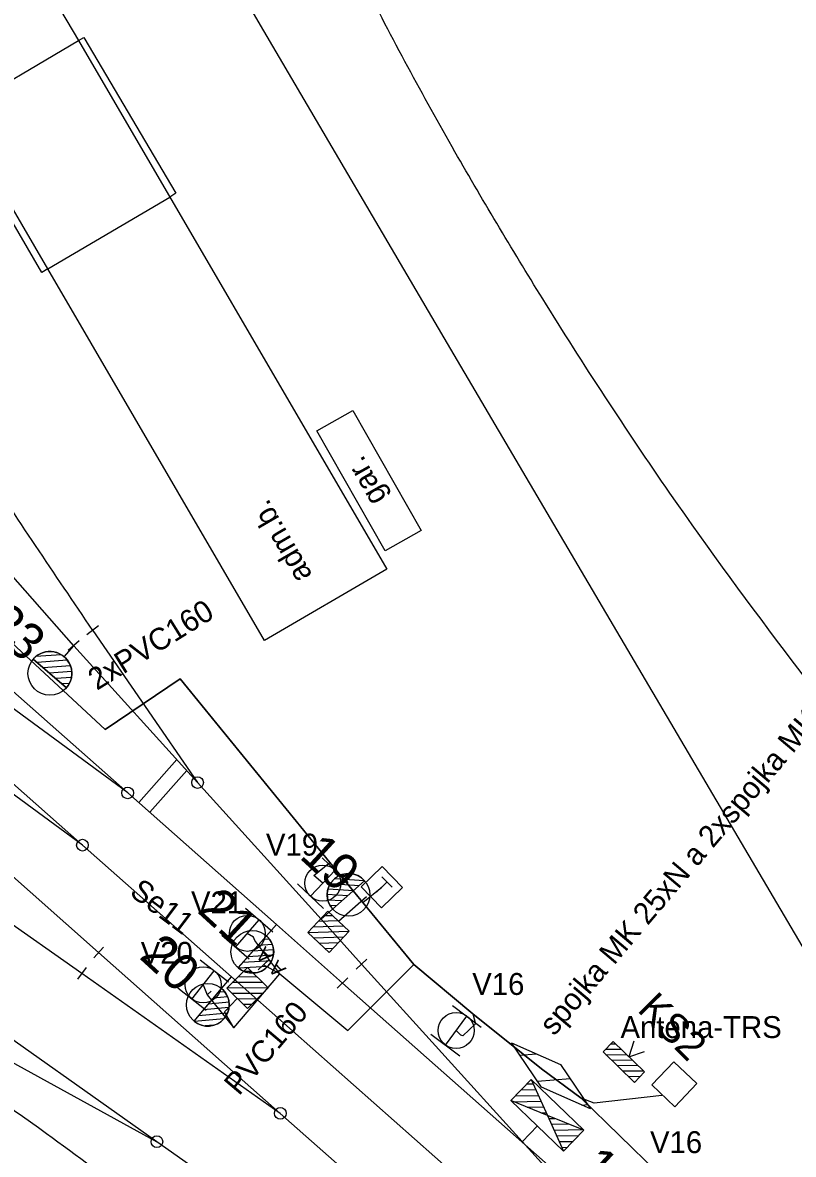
# Model space of a CAD drawing. Extents: x -496570 to -495506, y -1089156 to -1088046.
# Drawn here: x -495999 to -495946.2, y -1088619.5 to -1088542 of the extents above; entities that cross this region are included whole.
import ezdxf

# ---------------------------------------------------------------- set-up
doc = ezdxf.new("R2010")
doc.units = 0
for name, color, linetype in [('11', 7, 'Continuous'), ('14', 7, 'Continuous'), ('15', 7, 'Continuous'), ('20', 7, 'Continuous'), ('27', 7, 'Continuous'), ('39', 7, 'Continuous'), ('54', 7, 'Continuous'), ('PŘÍSTUPOVÉ_CESTY', 7, 'Continuous'), ('PŮVODNÍ_NÁVRH', 7, 'Continuous'), ('SEE', 7, 'Continuous')]:
    doc.layers.add(name, color=color, linetype=linetype)

msp = doc.modelspace()

# ---------------------------------------------------------------- linework, layer by layer
at = {"layer": '11'}
for points in [[(-495991.022, -1088595.386), (-495988.427, -1088592.439)], [(-495990.272, -1088596.046), (-495987.752, -1088593.184)]]:
    msp.add_lwpolyline(points, dxfattribs=at)
at = {"layer": '14'}
for p, q in [((-495993.785, -1088605.649), (-496022.225, -1088580.492)), ((-495994.931, -1088607.083), (-496005.328, -1088599.803)), ((-495978.542, -1088603.36), (-495975.783, -1088606.452)), ((-495981.593, -1088603.731), (-495977.082, -1088607.738))]:
    msp.add_line(p, q, dxfattribs=at)
for points in [[(-495941.228, -1088612.636), (-495960.706, -1088579.532), (-495969.885, -1088563.939), (-495982.474, -1088542.537), (-495998.352, -1088515.291)], [(-495984.692, -1088607.313), (-495963.796, -1088625.807), (-495948.204, -1088639.594)]]:
    msp.add_lwpolyline(points, dxfattribs=at)
for points in [[(-495937.589, -1088596.936), (-495954.664, -1088574.181), (-495963.373, -1088560.878), (-495969.575, -1088550.475), (-495975.882, -1088538.692), (-495984.212, -1088520.604)], [(-495994.179, -1088583.585), (-496001.925, -1088571.928), (-496007.411, -1088562.975), (-496027.558, -1088528.593)], [(-495939.964, -1088690.857), (-495942.044, -1088686.532), (-495949.093, -1088672.316), (-495953.81, -1088663.645), (-495962.754, -1088650.285), (-495972.743, -1088638.936), (-495985.077, -1088627.584), (-495997.355, -1088618.062), (-496006.199, -1088611.844)]]:
    msp.add_spline(points, degree=3, dxfattribs=at)
at = {"layer": '15'}
for p, q in [((-495978.475, -1088599.157), (-495976.688, -1088600.854)), ((-495979.278, -1088601.792), (-495977.582, -1088600.006)), ((-495980.172, -1088600.944), (-495978.385, -1088602.641)), ((-495983.721, -1088602.605), (-495981.862, -1088604.222)), ((-495984.409, -1088605.272), (-495982.791, -1088603.414)), ((-495978.732, -1088603.512), (-495977.405, -1088603.468)), ((-495978.37, -1088603.125), (-495977.791, -1088603.106)), ((-495979.457, -1088604.286), (-495976.63, -1088604.193)), ((-495979.095, -1088603.9), (-495977.017, -1088603.831)), ((-495985.338, -1088604.464), (-495983.479, -1088606.081)), ((-495979.07, -1088604.649), (-495976.992, -1088604.58)), ((-495978.682, -1088605.012), (-495977.355, -1088604.968)), ((-495978.296, -1088605.374), (-495977.717, -1088605.355)), ((-495986.833, -1088606.141), (-495984.896, -1088607.664)), ((-495987.387, -1088608.84), (-495985.865, -1088606.902)), ((-495982.926, -1088607.326), (-495984.254, -1088607.332)), ((-495983.303, -1088606.953), (-495983.881, -1088606.956)), ((-495988.356, -1088608.078), (-495986.419, -1088609.601)), ((-495982.172, -1088608.072), (-495985.001, -1088608.086)), ((-495982.549, -1088607.699), (-495984.628, -1088607.71)), ((-495982.545, -1088608.449), (-495984.624, -1088608.459)), ((-495982.919, -1088608.826), (-495984.247, -1088608.833)), ((-495983.292, -1088609.203), (-495983.87, -1088609.206)), ((-495969.549, -1088609.276), (-495967.576, -1088610.751)), ((-495970.038, -1088611.987), (-495968.562, -1088610.013)), ((-495971.024, -1088611.249), (-495969.051, -1088612.724))]:
    msp.add_line(p, q, dxfattribs=at)
for points in [[(-495978.09, -1088602.827), (-495976.63, -1088604.193), (-495977.997, -1088605.653), (-495979.457, -1088604.286)], [(-495978.09, -1088602.827), (-495976.63, -1088604.193), (-495977.997, -1088605.653), (-495979.457, -1088604.286)], [(-495983.579, -1088609.494), (-495985.001, -1088608.086), (-495983.594, -1088606.665), (-495982.172, -1088608.072)], [(-495983.579, -1088609.494), (-495985.001, -1088608.086), (-495983.594, -1088606.665), (-495982.172, -1088608.072)]]:
    msp.add_lwpolyline(points, close=True, dxfattribs=at)
for points in [[(-495978.09, -1088602.827), (-495976.63, -1088604.193), (-495977.997, -1088605.653), (-495979.457, -1088604.286), (-495978.09, -1088602.827)], [(-495978.09, -1088602.827), (-495976.63, -1088604.193), (-495977.997, -1088605.653), (-495979.457, -1088604.286), (-495978.09, -1088602.827)], [(-495983.579, -1088609.494), (-495985.001, -1088608.086), (-495983.594, -1088606.665), (-495982.172, -1088608.072), (-495983.579, -1088609.494)], [(-495983.579, -1088609.494), (-495985.001, -1088608.086), (-495983.594, -1088606.665), (-495982.172, -1088608.072), (-495983.579, -1088609.494)]]:
    msp.add_lwpolyline(points, dxfattribs=at)
for centre in [(-495978.427, -1088600.895), (-495983.598, -1088604.338), (-495986.624, -1088607.866), (-495969.298, -1088610.995)]:
    msp.add_circle(centre, 1.232, dxfattribs=at)
at = {"layer": '20'}
msp.add_line((-495982.125, -1088606.158), (-495982.855, -1088606.842), dxfattribs=at)
at = {"layer": '27'}
for p, q in [((-495993.78, -1088583.284), (-495994.578, -1088583.886)), ((-495996.14, -1088585.398), (-495995.487, -1088584.64)), ((-495995.118, -1088584.303), (-495995.856, -1088584.977)), ((-495998.255, -1088585.556), (-495995.982, -1088587.513)), ((-495995.982, -1088587.513), (-495998.255, -1088585.556)), ((-495996.34, -1088585.255), (-495998.076, -1088585.384)), ((-495995.93, -1088585.625), (-495997.995, -1088585.779)), ((-495995.717, -1088586.01), (-495997.567, -1088586.148)), ((-495995.628, -1088586.405), (-495997.138, -1088586.517)), ((-495995.647, -1088586.808), (-495996.709, -1088586.887)), ((-495995.788, -1088587.219), (-495996.281, -1088587.255)), ((-495976.869, -1088600.257), (-495976.279, -1088600.294)), ((-495977.911, -1088600.933), (-495975.932, -1088601.056)), ((-495975.577, -1088600.741), (-495977.772, -1088602.678)), ((-495975.569, -1088600.736), (-495977.764, -1088602.672)), ((-495977.602, -1088600.581), (-495975.598, -1088600.707)), ((-495975.57, -1088600.735), (-495975.569, -1088600.736)), ((-495978.127, -1088601.661), (-495976.718, -1088601.749)), ((-495978.07, -1088601.294), (-495976.325, -1088601.403)), ((-495977.773, -1088602.677), (-495978.542, -1088603.36)), ((-495978.089, -1088602.034), (-495977.11, -1088602.095)), ((-495977.943, -1088602.414), (-495977.503, -1088602.441)), ((-495982.275, -1088604.5), (-495981.593, -1088603.731)), ((-495984.233, -1088606.69), (-495982.283, -1088604.506)), ((-495984.225, -1088606.684), (-495982.277, -1088604.5)), ((-495981.885, -1088605.101), (-495982.864, -1088605.158)), ((-495982.075, -1088604.742), (-495982.516, -1088604.767)), ((-495993.455, -1088605.273), (-495994.115, -1088606.025)), ((-495981.816, -1088605.839), (-495983.562, -1088605.938)), ((-495981.804, -1088605.468), (-495983.213, -1088605.548)), ((-495982.196, -1088606.602), (-495984.201, -1088606.715)), ((-495981.931, -1088606.216), (-495983.91, -1088606.329)), ((-495975.415, -1088606.113), (-495976.151, -1088606.791)), ((-495994.631, -1088606.683), (-495995.231, -1088607.483)), ((-495985.352, -1088608.101), (-495984.692, -1088607.313)), ((-495984.232, -1088606.69), (-495984.233, -1088606.69)), ((-495982.886, -1088607.011), (-495983.476, -1088607.045)), ((-495976.723, -1088607.39), (-495977.441, -1088608.086)), ((-495987.246, -1088610.346), (-495985.36, -1088608.108)), ((-495987.238, -1088610.341), (-495985.353, -1088608.101)), ((-495984.945, -1088608.691), (-495985.922, -1088608.776)), ((-495985.145, -1088608.337), (-495985.585, -1088608.375)), ((-495984.854, -1088609.426), (-495986.596, -1088609.575)), ((-495984.853, -1088609.055), (-495986.259, -1088609.176)), ((-495987.245, -1088610.347), (-495987.246, -1088610.346)), ((-495985.213, -1088610.2), (-495987.213, -1088610.371)), ((-495984.958, -1088609.806), (-495986.934, -1088609.976)), ((-496003.75, -1088610.956), (-495989.792, -1088618.606)), ((-495985.89, -1088610.629), (-495986.479, -1088610.679)), ((-495964.839, -1088615.056), (-495963.853, -1088615.036)), ((-495964.447, -1088614.648), (-495964.033, -1088614.639)), ((-495965.37, -1088615.867), (-495963.494, -1088615.828)), ((-495965.23, -1088615.464), (-495963.673, -1088615.431)), ((-495964.429, -1088616.248), (-495963.315, -1088616.225)), ((-495963.487, -1088616.628), (-495963.135, -1088616.621)), ((-495962.956, -1088617.015), (-495962.55, -1088617.007)), ((-495962.777, -1088617.412), (-495961.609, -1088617.387)), ((-495963.74, -1088617.53), (-495964.79, -1088618.616)), ((-495962.597, -1088617.808), (-495960.668, -1088617.768)), ((-495962.417, -1088618.204), (-495960.9, -1088618.173)), ((-495962.237, -1088618.6), (-495961.292, -1088618.581)), ((-495962.058, -1088618.997), (-495961.683, -1088618.989))]:
    msp.add_line(p, q, dxfattribs=at)
for points in [[(-495995.487, -1088584.64), (-496003.83, -1088575.183), (-496011.29, -1088565.037)], [(-495981.593, -1088603.731), (-495991.789, -1088594.718), (-496006.781, -1088581.466)], [(-495991.789, -1088594.718), (-496007.924, -1088582.875)], [(-495994.179, -1088583.585), (-495987.005, -1088594.01)], [(-495978.542, -1088603.36), (-495987.005, -1088594.01), (-495995.487, -1088584.64)], [(-495984.692, -1088607.313), (-495994.886, -1088598.298), (-496009.888, -1088585.031)], [(-495994.886, -1088598.298), (-496011.01, -1088586.449)], [(-495968.895, -1088627.681), (-495981.34, -1088616.665), (-495993.785, -1088605.649)], [(-495953.783, -1088630.732), (-495975.783, -1088606.452)], [(-495981.34, -1088616.665), (-495994.931, -1088607.083)], [(-495977.082, -1088607.738), (-495952.499, -1088629.495)], [(-495981.197, -1088624.677), (-495989.792, -1088618.606), (-496003.341, -1088609.037)], [(-495964.163, -1088614.352), (-495963.052, -1088616.804), (-495965.548, -1088615.795), (-495964.163, -1088614.352)], [(-495960.555, -1088617.813), (-495963.052, -1088616.804), (-495961.94, -1088619.257), (-495960.555, -1088617.813)]]:
    msp.add_lwpolyline(points, dxfattribs=at)
msp.add_lwpolyline([(-495964.163, -1088614.352), (-495960.555, -1088617.813), (-495961.94, -1088619.257), (-495965.548, -1088615.795)], close=True, dxfattribs=at)
for centre, radius in [((-495997.118, -1088586.534), 1.5), ((-495987.005, -1088594.01), 0.4), ((-495991.789, -1088594.718), 0.4), ((-495994.886, -1088598.298), 0.4), ((-495976.668, -1088601.704), 1.462), ((-495983.257, -1088605.598), 1.462), ((-495986.302, -1088609.227), 1.462), ((-495981.34, -1088616.665), 0.4), ((-495989.792, -1088618.606), 0.4)]:
    msp.add_circle(centre, radius, dxfattribs=at)
for centre, radius, start, end in [((-495997.118, -1088586.534), 1.5, 319.26705, 139.26705), ((-495976.667, -1088601.704), 1.464, 41.45443, 221.41528), ((-495983.258, -1088605.598), 1.464, 228.28161, 48.24246), ((-495986.303, -1088609.227), 1.464, 229.92658, 49.88743)]:
    msp.add_arc(centre, radius, start, end, dxfattribs=at)
at = {"layer": '39'}
for points in [[(-495974.045, -1088579.399), (-495982.418, -1088584.284), (-495997.256, -1088558.819), (-496003.517, -1088548.12), (-496034.293, -1088496.252), (-496025.968, -1088491.27), (-495995.168, -1088543.196), (-495974.045, -1088579.399)], [(-495995.168, -1088543.196), (-495994.796, -1088542.976), (-495988.499, -1088553.653), (-495988.912, -1088553.916)], [(-496003.517, -1088548.12), (-495995.168, -1088543.196)], [(-495997.256, -1088558.819), (-495997.66, -1088559.09), (-496003.906, -1088548.391), (-496003.517, -1088548.12)], [(-495997.256, -1088558.819), (-495988.912, -1088553.916)], [(-495978.849, -1088569.915), (-495976.363, -1088568.525), (-495971.703, -1088576.746), (-495974.166, -1088578.147), (-495978.849, -1088569.915)]]:
    msp.add_lwpolyline(points, dxfattribs=at)
msp.add_lwpolyline([(-495955.91, -1088614.71), (-495954.405, -1088613.125), (-495952.82, -1088614.63), (-495954.32, -1088616.22)], close=True, dxfattribs=at)
at = {"layer": '54'}
for p, q in [((-495977.36, -1088603.51), (-495975.43, -1088601.82)), ((-495981.379, -1088607.106), (-495982.49, -1088606.5)), ((-495986.345, -1088608.554), (-495986.08, -1088608.29))]:
    msp.add_line(p, q, dxfattribs=at)
for points in [[(-496012.78, -1088570.83), (-496012.549, -1088570.954), (-496010.733, -1088573.476), (-496000.372, -1088583.843), (-495993.339, -1088590.372), (-495988.204, -1088586.901), (-495977.95, -1088599.48), (-495977.304, -1088600.272), (-495972.198, -1088606.466), (-495968.157, -1088609.856), (-495963.452, -1088613.618), (-495960.741, -1088615.623), (-495955.49, -1088620.73), (-495954.76, -1088621.51), (-495953.449, -1088622.609), (-495941.984, -1088632.338)], [(-495978.43, -1088600.899), (-495979.05, -1088600.37), (-495977.95, -1088599.48)], [(-495981.379, -1088607.106), (-495983.09, -1088604.83), (-495983.186, -1088604.589), (-495983.6, -1088604.343)], [(-495986.626, -1088607.871), (-495986.345, -1088608.554), (-495984.516, -1088610.8), (-495981.379, -1088607.106), (-495976.725, -1088610.987), (-495972.198, -1088606.466)], [(-495984.516, -1088610.8), (-495985.17, -1088609.71), (-495984.29, -1088608.79)], [(-495968.157, -1088609.856), (-495967.97, -1088610.53), (-495968.85, -1088611.35), (-495968.99, -1088611.3), (-495969.3, -1088611)]]:
    msp.add_lwpolyline(points, dxfattribs=at)
at = {"layer": 'PŘÍSTUPOVÉ_CESTY'}
for p, q in [((-495974.032, -1088600.818), (-495974.75, -1088601.514)), ((-495974.381, -1088600.459), (-495973.684, -1088601.176)), ((-495958.698, -1088611.897), (-495958.39, -1088611.893)), ((-495959.067, -1088612.277), (-495958.01, -1088612.262)), ((-495959.043, -1088612.652), (-495957.629, -1088612.632)), ((-495958.663, -1088613.022), (-495957.249, -1088613.002)), ((-495958.283, -1088613.391), (-495956.869, -1088613.371)), ((-495957.902, -1088613.761), (-495956.488, -1088613.742)), ((-495957.522, -1088614.131), (-495956.674, -1088614.119)), ((-495957.142, -1088614.5), (-495957.043, -1088614.499))]:
    msp.add_line(p, q, dxfattribs=at)
for points in [[(-495974.371, -1088599.752), (-495972.977, -1088601.186), (-495974.411, -1088602.58), (-495975.805, -1088601.146), (-495974.371, -1088599.752)], [(-495958.546, -1088611.741), (-495956.395, -1088613.832), (-495957.092, -1088614.549), (-495959.243, -1088612.458), (-495958.546, -1088611.741)], [(-495957.132, -1088611.721), (-495957.47, -1088612.787), (-495956.415, -1088612.418)]]:
    msp.add_lwpolyline(points, dxfattribs=at)
msp.add_lwpolyline([(-495958.546, -1088611.741), (-495956.395, -1088613.832), (-495957.092, -1088614.549), (-495959.243, -1088612.458)], close=True, dxfattribs=at)
at = {"layer": 'PŮVODNÍ_NÁVRH'}
for p, q in [((-495993.339, -1088590.372), (-495988.204, -1088586.901)), ((-495976.725, -1088610.987), (-495972.198, -1088606.466)), ((-495984.516, -1088610.8), (-495981.379, -1088607.106))]:
    msp.add_line(p, q, dxfattribs=at)
at = {"layer": 'SEE'}
for p, q in [((-495975.687, -1088602.234), (-495974.391, -1088601.166)), ((-495964.947, -1088612.688), (-495963.822, -1088612.587)), ((-495963.729, -1088614.462), (-495961.501, -1088614.287)), ((-495960.693, -1088616.097), (-495960.281, -1088616.06))]:
    msp.add_line(p, q, dxfattribs=at)
msp.add_lwpolyline([(-495955.217, -1088615.433), (-495959.856, -1088615.966), (-495960.741, -1088615.623), (-495963.452, -1088613.618), (-495968.157, -1088609.856), (-495972.198, -1088606.466), (-495975.687, -1088602.234), (-495977.304, -1088600.272), (-495988.204, -1088586.901), (-495993.339, -1088590.372), (-496000.372, -1088583.843), (-496010.733, -1088573.476), (-496012.549, -1088570.954), (-496014.475, -1088569.283), (-496015.783, -1088567.718)], dxfattribs=at)
msp.add_lwpolyline([(-495965.514, -1088611.837), (-495962.156, -1088613.313), (-495960.102, -1088616.353), (-495963.46, -1088614.877)], close=True, dxfattribs=at)

# ---------------------------------------------------------------- texts
at = {"layer": '15'}
for s, p in [('V19', (-495982.324, -1088599.012)), ('V21', (-495987.454, -1088602.965)), ('V20', (-495990.899, -1088606.424)), ('V16', (-495968.198, -1088608.553)), ('V16', (-495956.024, -1088619.386))]:
    msp.add_text(s, height=1.5, dxfattribs=at).set_placement(p)
at = {"layer": '20'}
for s, height, rotation, p in [('Se11', 1.5, 323.04383, (-495991.734, -1088601.68)), ('  A A', 1, 133.14761, (-495980.393, -1088607.3))]:
    msp.add_text(s, height=height, rotation=rotation, dxfattribs=at).set_placement(p)
at = {"layer": '27'}
for s, p in [('23', (-496001.619, -1088583.324)), ('19', (-495980.104, -1088599.136)), ('21', (-495987.103, -1088602.838)), ('20', (-495991.066, -1088605.998)), ('16', (-495961.051, -1088620.555))]:
    msp.add_text(s, height=2.5, rotation=317.44522, dxfattribs=at).set_placement(p)
at = {"layer": '39'}
for s, rotation, p in [('gar.', 119.63458, (-495974.014, -1088574.503)), ('adm.b.', 120.22859, (-495979.116, -1088579.794))]:
    msp.add_text(s, height=1.5, rotation=rotation, dxfattribs=at).set_placement(p)
msp.add_text('Antena-TRS', height=1.5, dxfattribs=at).set_placement((-495958.047, -1088611.506))
at = {"layer": '54'}
for s, rotation, p in [('2xPVC160', 31.8898, (-495993.899, -1088587.731)), ('PVC160', 49.81743, (-495984.169, -1088615.511))]:
    msp.add_text(s, height=1.5, rotation=rotation, dxfattribs=at).set_placement(p)
at = {"layer": 'PŘÍSTUPOVÉ_CESTY'}
msp.add_text('KS2', height=2, rotation=314.76049, dxfattribs=at).set_placement((-495956.959, -1088609.617))
at = {"layer": 'SEE'}
msp.add_text('spojka MK 25xN a 2xspojka MK 5xN', height=1.5, rotation=49.82097, dxfattribs=at).set_placement((-495962.589, -1088611.419))

doc.saveas('drawing.dxf')
